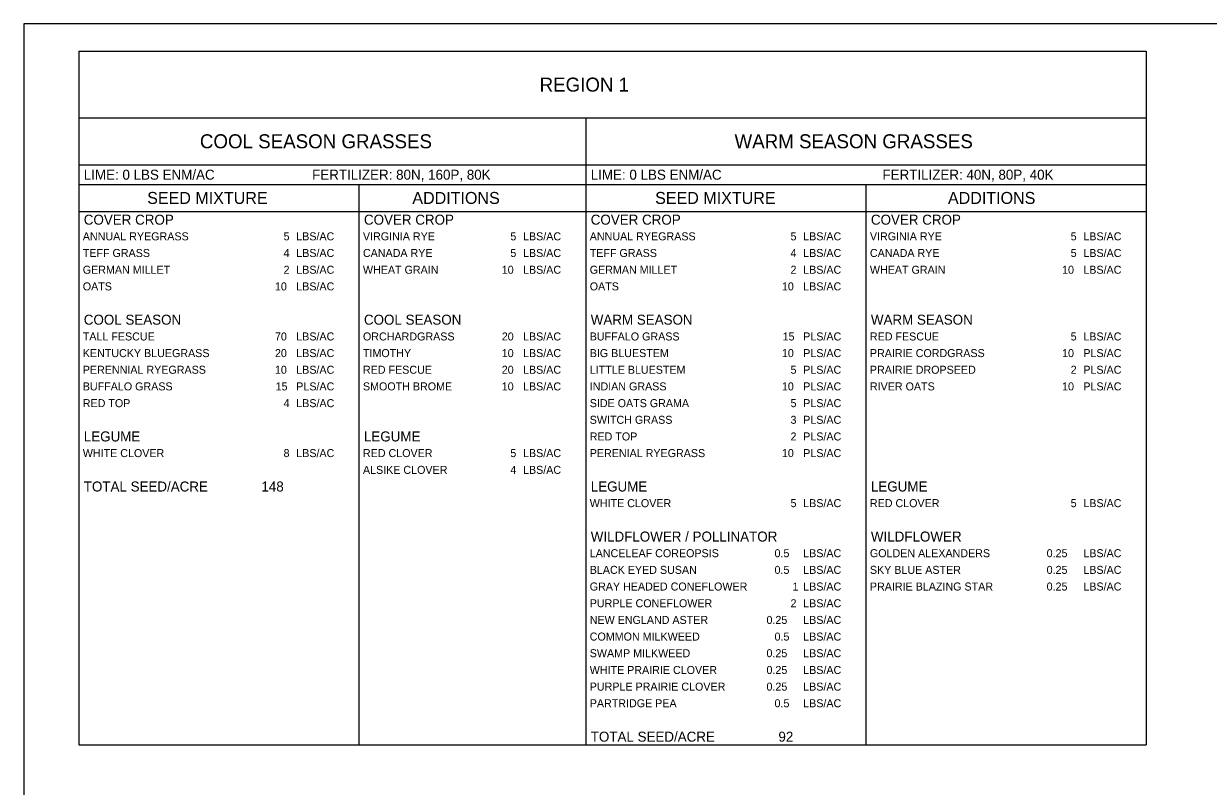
# Model space of a CAD drawing. Extents: x 0 to 3125, y 0 to 2037.
# Drawn here: x 0 to 1074, y 1346 to 2037 of the extents above; entities that cross this region are included whole.
import ezdxf

# ---------------------------------------------------------------- set-up
doc = ezdxf.new("R2010")
doc.units = 0
for name, color, linetype in [('Common-Notes', 7, 'Continuous'), ('Draft_Named_Boundary', 7, 'Continuous'), ('Grid_Line-Main', 7, 'Continuous')]:
    doc.layers.add(name, color=color, linetype=linetype)

msp = doc.modelspace()

# ---------------------------------------------------------------- linework, layer by layer
at = {"layer": 'Draft_Named_Boundary'}
msp.add_lwpolyline([(0, 0), (3125, 0), (3125, 2037.5), (0, 2037.5)], close=True, dxfattribs=at)
at = {"layer": 'Grid_Line-Main'}
for p, q in [((50, 2012.5), (1018, 2012.5)), ((50, 2012.5), (50, 1383.3)), ((1018, 2012.5), (1018, 1383.3)), ((50, 1952), (1018, 1952)), ((509.8, 1952), (509.8, 1383.3)), ((50, 1909.6), (1018, 1909.6)), ((50, 1891.5), (1018, 1891.5)), ((304.1, 1891.5), (304.1, 1383.3)), ((763.9, 1891.5), (763.9, 1383.3)), ((50, 1867.3), (1018, 1867.3)), ((50, 1383.3), (1018, 1383.3))]:
    msp.add_line(p, q, dxfattribs=at)

# ---------------------------------------------------------------- texts
at = {"layer": 'Common-Notes'}
for s, height, p in [(' REGION 1', 12.7, (463.2, 1975.9)), ('COOL SEASON GRASSES', 12.705, (159.8, 1924.5)), ('WARM SEASON GRASSES', 12.705, (644.7, 1924.5)), ('LIME: 0 LBS ENM/AC', 9.075, (54.5, 1896)), ('FERTILIZER: 80N, 160P, 80K', 9.075, (261.6, 1896)), ('LIME: 0 LBS ENM/AC', 9.075, (514.3, 1896)), ('FERTILIZER: 40N, 80P, 40K', 9.075, (778.9, 1896)), ('SEED MIXTURE', 10.89, (112, 1874)), ('ADDITIONS ', 10.89, (352.5, 1874)), ('SEED MIXTURE', 10.89, (572.7, 1874)), ('ADDITIONS ', 10.89, (838.3, 1874)), ('COVER CROP', 9.08, (54.5, 1855.2)), ('COVER CROP', 9.08, (308.6, 1855.2)), ('COVER CROP', 9.08, (514.3, 1855.2)), ('COVER CROP', 9.08, (768.4, 1855.2)), ('ANNUAL RYEGRASS', 7.26, (53.6, 1841)), ('5', 7.26, (235.7, 1841)), ('LBS/AC', 7.26, (247.2, 1841)), ('VIRGINIA RYE', 7.26, (307.7, 1841)), ('5', 7.26, (441.4, 1841)), ('LBS/AC', 7.26, (452.9, 1841)), ('ANNUAL RYEGRASS', 7.26, (513.4, 1841)), ('5', 7.26, (695.5, 1841)), ('LBS/AC', 7.26, (707, 1841)), ('VIRGINIA RYE', 7.26, (767.5, 1841)), ('5', 7.26, (949.6, 1841)), ('LBS/AC', 7.26, (961.1, 1841)), ('TEFF GRASS', 7.26, (53.6, 1825.9)), ('4', 7.26, (235.7, 1825.9)), ('LBS/AC', 7.26, (247.2, 1825.9)), ('CANADA RYE', 7.26, (307.7, 1825.9)), ('5', 7.26, (441.4, 1825.9)), ('LBS/AC', 7.26, (452.9, 1825.9)), ('TEFF GRASS', 7.26, (513.4, 1825.9)), ('4', 7.26, (695.5, 1825.9)), ('LBS/AC', 7.26, (707, 1825.9)), ('CANADA RYE', 7.26, (767.5, 1825.9)), ('5', 7.26, (949.6, 1825.9)), ('LBS/AC', 7.26, (961.1, 1825.9)), ('GERMAN MILLET', 7.26, (53.6, 1810.7)), ('2', 7.26, (235.7, 1810.7)), ('LBS/AC', 7.26, (247.2, 1810.7)), ('WHEAT GRAIN', 7.26, (307.7, 1810.7)), ('10', 7.26, (433.6, 1810.7)), ('LBS/AC', 7.26, (452.9, 1810.7)), ('GERMAN MILLET', 7.26, (513.4, 1810.7)), ('2', 7.26, (695.5, 1810.7)), ('LBS/AC', 7.26, (707, 1810.7)), ('WHEAT GRAIN', 7.26, (767.5, 1810.7)), ('10', 7.26, (941.8, 1810.7)), ('LBS/AC', 7.26, (961.1, 1810.7)), ('OATS', 7.26, (53.6, 1795.6)), ('10', 7.26, (227.9, 1795.6)), ('LBS/AC', 7.26, (247.2, 1795.6)), ('OATS', 7.26, (513.4, 1795.6)), ('10', 7.26, (687.7, 1795.6)), ('LBS/AC', 7.26, (707, 1795.6)), ('COOL SEASON', 9.075, (54.5, 1764.5)), ('COOL SEASON', 9.075, (308.6, 1764.5)), ('WARM SEASON', 9.075, (514.3, 1764.5)), ('WARM SEASON', 9.075, (768.4, 1764.5)), ('TALL FESCUE', 7.26, (53.6, 1750.2)), ('70', 7.26, (227.9, 1750.2)), ('LBS/AC', 7.26, (247.2, 1750.2)), ('ORCHARDGRASS', 7.26, (307.7, 1750.2)), ('20', 7.26, (433.6, 1750.2)), ('LBS/AC', 7.26, (452.9, 1750.2)), ('BUFFALO GRASS', 7.26, (513.4, 1750.2)), ('15', 7.26, (688.3, 1750.2)), ('PLS/AC', 7.26, (707, 1750.2)), ('RED FESCUE', 7.26, (767.5, 1750.2)), ('5', 7.26, (949.6, 1750.2)), ('LBS/AC', 7.26, (961.1, 1750.2)), ('KENTUCKY BLUEGRASS', 7.26, (53.6, 1735.1)), ('20', 7.26, (227.9, 1735.1)), ('LBS/AC', 7.26, (247.2, 1735.1)), ('TIMOTHY', 7.26, (307.7, 1735.1)), ('10', 7.26, (433.6, 1735.1)), ('LBS/AC', 7.26, (452.9, 1735.1)), ('BIG BLUESTEM', 7.26, (513.4, 1735.1)), ('10', 7.26, (687.7, 1735.1)), ('PLS/AC', 7.26, (707, 1735.1)), ('PRAIRIE CORDGRASS', 7.26, (767.5, 1735.1)), ('10', 7.26, (941.8, 1735.1)), ('PLS/AC', 7.26, (961.1, 1735.1)), ('PERENNIAL RYEGRASS', 7.26, (53.6, 1720)), ('10', 7.26, (227.9, 1720)), ('LBS/AC', 7.26, (247.2, 1720)), ('RED FESCUE', 7.26, (307.7, 1720)), ('20', 7.26, (433.6, 1720)), ('LBS/AC', 7.26, (452.9, 1720)), ('LITTLE BLUESTEM', 7.26, (513.4, 1720)), ('5', 7.26, (695.5, 1720)), ('PLS/AC', 7.26, (707, 1720)), ('PRAIRIE DROPSEED', 7.26, (767.5, 1720)), ('2', 7.26, (949.6, 1720)), ('PLS/AC', 7.26, (961.1, 1720)), ('BUFFALO GRASS', 7.26, (53.6, 1704.9)), ('15', 7.26, (228.5, 1704.9)), ('PLS/AC', 7.26, (247.2, 1704.9)), ('SMOOTH BROME', 7.26, (307.7, 1704.9)), ('10', 7.26, (433.6, 1704.9)), ('LBS/AC', 7.26, (452.9, 1704.9)), ('INDIAN GRASS', 7.26, (513.4, 1704.9)), ('10', 7.26, (687.7, 1704.9)), ('PLS/AC', 7.26, (707, 1704.9)), ('RIVER OATS', 7.26, (767.5, 1704.9)), ('10', 7.26, (941.8, 1704.9)), ('PLS/AC', 7.26, (961.1, 1704.9)), ('RED TOP', 7.26, (53.6, 1689.7)), ('4', 7.26, (235.7, 1689.7)), ('LBS/AC', 7.26, (247.2, 1689.7)), ('SIDE OATS GRAMA', 7.26, (513.4, 1689.7)), ('5', 7.26, (695.5, 1689.7)), ('PLS/AC', 7.26, (707, 1689.7)), ('SWITCH GRASS', 7.26, (513.4, 1674.6)), ('3', 7.26, (695.5, 1674.6)), ('PLS/AC', 7.26, (707, 1674.6)), ('LEGUME', 9.08, (54.5, 1658.6)), ('LEGUME', 9.08, (308.6, 1658.6)), ('RED TOP', 7.26, (513.4, 1659.5)), ('2', 7.26, (695.5, 1659.5)), ('PLS/AC', 7.26, (707, 1659.5)), ('WHITE CLOVER', 7.26, (53.6, 1644.4)), ('8', 7.26, (235.7, 1644.4)), ('LBS/AC', 7.26, (247.2, 1644.4)), ('RED CLOVER', 7.26, (307.7, 1644.4)), ('5', 7.26, (441.4, 1644.4)), ('LBS/AC', 7.26, (452.9, 1644.4)), ('PERENIAL RYEGRASS', 7.26, (513.4, 1644.4)), ('10', 7.26, (687.7, 1644.4)), ('PLS/AC', 7.26, (707, 1644.4)), ('ALSIKE CLOVER', 7.26, (307.7, 1629.2)), ('4', 7.26, (441.4, 1629.2)), ('LBS/AC', 7.26, (452.9, 1629.2)), ('TOTAL SEED/ACRE', 9.075, (54.5, 1613.2)), ('148', 9.08, (215.6, 1613.2)), ('LEGUME ', 9.08, (514.3, 1613.2)), ('LEGUME', 9.08, (768.4, 1613.2)), ('WHITE CLOVER', 7.26, (513.4, 1599)), ('5', 7.26, (695.5, 1599)), ('LBS/AC', 7.26, (707, 1599)), ('RED CLOVER', 7.26, (767.5, 1599)), ('5', 7.26, (949.6, 1599)), ('LBS/AC', 7.26, (961.1, 1599)), ('WILDFLOWER / POLLINATOR ', 9.075, (514.3, 1567.8)), ('WILDFLOWER', 9.08, (768.4, 1567.8)), ('LANCELEAF COREOPSIS', 7.26, (513.4, 1553.6)), ('0.5', 7.26, (681, 1553.6)), ('LBS/AC', 7.26, (707, 1553.6)), ('GOLDEN ALEXANDERS', 7.26, (767.5, 1553.6)), ('0.25', 7.26, (927.8, 1553.6)), ('LBS/AC', 7.26, (961.1, 1553.6)), ('BLACK EYED SUSAN', 7.26, (513.4, 1538.5)), ('0.5', 7.26, (681, 1538.5)), ('LBS/AC', 7.26, (707, 1538.5)), ('SKY BLUE ASTER', 7.26, (767.5, 1538.5)), ('0.25', 7.26, (927.8, 1538.5)), ('LBS/AC', 7.26, (961.1, 1538.5)), ('GRAY HEADED CONEFLOWER', 7.26, (513.4, 1523.4)), ('1', 7.26, (697.3, 1523.4)), ('LBS/AC', 7.26, (707, 1523.4)), ('PRAIRIE BLAZING STAR', 7.26, (767.5, 1523.4)), ('0.25', 7.26, (927.8, 1523.4)), ('LBS/AC', 7.26, (961.1, 1523.4)), ('PURPLE CONEFLOWER', 7.26, (513.4, 1508.2)), ('2', 7.26, (695.5, 1508.2)), ('LBS/AC', 7.26, (707, 1508.2)), ('NEW ENGLAND ASTER', 7.26, (513.4, 1493.1)), ('0.25', 7.26, (673.7, 1493.1)), ('LBS/AC', 7.26, (707, 1493.1)), ('COMMON MILKWEED', 7.26, (513.4, 1478)), ('0.5', 7.26, (681, 1478)), ('LBS/AC', 7.26, (707, 1478)), ('SWAMP MILKWEED', 7.26, (513.4, 1462.9)), ('0.25', 7.26, (673.7, 1462.9)), ('LBS/AC', 7.26, (707, 1462.9)), ('WHITE PRAIRIE CLOVER', 7.26, (513.4, 1447.7)), ('0.25', 7.26, (673.7, 1447.7)), ('LBS/AC', 7.26, (707, 1447.7)), ('PURPLE PRAIRIE CLOVER', 7.26, (513.4, 1432.6)), ('0.25', 7.26, (673.7, 1432.6)), ('LBS/AC', 7.26, (707, 1432.6)), ('PARTRIDGE PEA', 7.26, (513.4, 1417.5)), ('0.5', 7.26, (681, 1417.5)), ('LBS/AC', 7.26, (707, 1417.5)), ('TOTAL SEED/ACRE', 9.075, (514.3, 1386.3)), ('92', 9.08, (684.5, 1386.3))]:
    msp.add_text(s, height=height, dxfattribs=at).set_placement(p)

doc.saveas('drawing.dxf')
